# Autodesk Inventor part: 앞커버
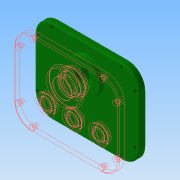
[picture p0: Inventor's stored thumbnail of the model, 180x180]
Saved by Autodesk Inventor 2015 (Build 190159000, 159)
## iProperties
Created: 2016-12
Part Number: 앞커버
Material: 알루미늄 6061
Document SubType Name: Modeling
Designer: mduedu
Density: 2.71 g/cm^3
Mass: 710.865 g
Surface Area: 632.218 cm^2
Volume: 262.312 cm^3
Appearance: 진녹색
Author: mduedu
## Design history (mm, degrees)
sketch "스케치1"
  geometry: L1 (-90, 42)-(-90, -42); L2 (-60, 72)-(60, 72); L3 (90, 42)-(90, -42); L4 (60, -72)-(-60, -72); A1 r 30 centre (-60, -42) between (-90, -42) and (-60, -72); A2 r 30 centre (60, 42) between (90, 42) and (60, 72); A3 r 30 centre (60, -42) between (60, -72) and (90, -42); A4 r 30 centre (-60, 42) between (-60, 72) and (-90, 42); 1 further point
  constraints: 8 end point, 8 point on circle, 8 tangent, 4 centre point, 3 equal radius, 2 perpendicular, 1 horizontal
  dimensions: "d89" = 30 radius of A2; "d116" = 180 distance between parallel lines of L3 L1; "d117" = 90 distance from line of point (0, 0) L1; "d118" = 72 distance from line of L2 point (0, 0); "d119" = 144 distance between parallel lines of L4 L2
extrude "돌출1" new body sketch "스케치1" distance "d3" = 10; taper "d4" = 0 deg
sketch "스케치2"
  geometry: C1 r 21 at (0, 26); 1 further point
  constraints: 1 centre point, 1 vertical alignment
  dimensions: "d5" = 42 diameter of C1; "d7" = 26 distance of C1.centre point (0, 0)
extrude "돌출2" join sketch "스케치2" distance "d8" = 7; taper "d9" = 0 deg
sketch "스케치3"
  geometry: C1 r 15 at (0, -28.87); C2 r 21 at (0, 26) reference; C3 r 15 at (-45.552, -28.87); C4 r 15 at (45.552, -28.87); 1 further point
  constraints: 3 centre point, 2 horizontal alignment, 1 vertical alignment
  dimensions: "d10" = 30 diameter of C1; "d71" = 54.87 distance of C1.centre C2.centre; "d120" = 30 diameter of C3; "d121" = 30 diameter of C4; "d122" = 45.552 distance of C3.centre C1.centre; "d123" = 45.552 distance of C4.centre C1.centre
extrude "돌출3" join sketch "스케치3" distance "d12" = 7; taper "d13" = 0 deg
sketch "스케치4"
  geometry: C1 r 21 at (0, 26) reference; C2 r 28 at (0, 26); 1 further point
  constraints: 1 centre point, 1 coincident
  dimensions: "d14" = 56 diameter of C2
extrude "돌출4" join sketch "스케치4" distance "d15" = 7; taper "d16" = -5 deg
hole "구멍1" diameter "d19" = 35; stored, may be unused: countersink angle "d23" = 90 deg, drill point angle "d25" = 0 deg; dims "d17" = 10, "d18" = 10, "d20" = 6, "d21" = 4, "d22" = 2, "d24" = 10
hole "구멍2" diameter "d28" = 22; stored, may be unused: countersink angle "d32" = 90 deg, drill point angle "d34" = 0 deg; dims "d26" = 10, "d27" = 10, "d29" = 6, "d30" = 4, "d31" = 2, "d33" = 7
hole "구멍8" diameter "d98" = 22; stored, may be unused: countersink angle "d102" = 90 deg, drill point angle "d104" = 0 deg; dims "d99" = 6, "d100" = 4, "d101" = 2, "d103" = 7, "d137" = 10, "d138" = 10
hole "구멍10" diameter "d128" = 22; stored, may be unused: countersink angle "d132" = 90 deg, drill point angle "d134" = 0 deg; dims "d129" = 6, "d130" = 4, "d131" = 2, "d133" = 7, "d135" = 10, "d136" = 10
hole "구멍3" diameter "d37" = 19; stored, may be unused: countersink angle "d41" = 90 deg, drill point angle "d43" = 0 deg; dims "d38" = 6, "d39" = 4, "d40" = 2, "d42" = 1, "d139" = 10, "d140" = 10
hole "구멍9" diameter "d107" = 19; stored, may be unused: countersink angle "d111" = 90 deg, drill point angle "d113" = 0 deg; dims "d108" = 6, "d109" = 4, "d110" = 2, "d112" = 1, "d141" = 10, "d142" = 10
hole "구멍11" diameter "d145" = 19; stored, may be unused: countersink angle "d149" = 90 deg, drill point angle "d151" = 0 deg; dims "d143" = 10, "d144" = 10, "d146" = 6, "d147" = 4, "d148" = 2, "d150" = 1
hole "구멍4" diameter "d46" = 32; stored, may be unused: countersink angle "d50" = 90 deg, drill point angle "d52" = 0 deg; dims "d47" = 6, "d48" = 4, "d49" = 2, "d51" = 8.3, "d154" = 10, "d155" = 10
hole "구멍5" diameter "d55" = 25; stored, may be unused: countersink angle "d59" = 90 deg, drill point angle "d61" = 0 deg; dims "d53" = 10, "d54" = 10, "d56" = 6, "d57" = 4, "d58" = 2, "d60" = 8
fillet "모깎기1" dims "d62" = 0.3
fillet "모깎기2" dims "d63" = 2
chamfer "모따기1" distance "d64" = 1; stored, may be unused: second distance "d65" = 2, angle "d66" = 45 deg
chamfer "모따기2" distance "d152" = 0.8; stored, may be unused: second distance "d153" = 2, angle "d156" = 30 deg
fillet "모깎기4" dims "d68" = 2
fillet "모깎기5" dims "d69" = 2
fillet "모깎기7" dims "d157" = 2
sketch "스케치5"
  geometry: L1 (60, 72)-(-60, 72) reference; L2 (90, -42)-(90, 42) reference; L3 (-60, -72)-(60, -72) reference; L4 (-90, 42)-(-90, -42) reference; L5 (-84, 42)-(-84, -42); L6 (-60, -66)-(60, -66); L7 (84, -42)-(84, 42); L8 (60, 66)-(-60, 66); A1 r 30 centre (60, 42) between (90, 42) and (60, 72) reference; A2 r 30 centre (60, -42) between (60, -72) and (90, -42) reference; A3 r 30 centre (-60, -42) between (-90, -42) and (-60, -72) reference; A4 r 30 centre (-60, 42) between (-60, 72) and (-90, 42) reference; A5 r 24 centre (-60, -42) between (-84, -42) and (-60, -66); A6 r 24 centre (60, -42) between (60, -66) and (84, -42); A7 r 24 centre (60, 42) between (84, 42) and (60, 66); A8 r 24 centre (-60, 42) between (-60, 66) and (-84, 42)
  constraints: 8 end point, 8 point on circle, 4 centre point, 7 other
  dimensions: "d93" = 6 distance between parallel lines of L5 L4
sketch "스케치7"
  geometry: L1 (60, 66)-(-60, 66) reference; L2 (84, -42)-(84, 42) reference; L3 (-60, -66)-(60, -66) reference; L4 (-84, 42)-(-84, -42) reference; A1 r 24 centre (60, 42) between (84, 42) and (60, 66) reference; A2 r 24 centre (60, -42) between (60, -66) and (84, -42) reference; A3 r 24 centre (-60, -42) between (-84, -42) and (-60, -66) reference; A4 r 24 centre (-60, 42) between (-60, 66) and (-84, 42) reference; 8 further points
  constraints: 8 coincident
hole "구멍7" sketch "스케치7" at (-84, 42), (-84, -42), (-60, -66), (60, -66), (84, -42), (84, 42), (60, 66), (-60, 66) diameter "d80" = 4.5; stored, may be unused: countersink angle "d84" = 90 deg, drill point angle "d86" = 0 deg; dims "d81" = 6, "d82" = 8, "d83" = 4.6, "d85" = 8
node "솔리드1"
